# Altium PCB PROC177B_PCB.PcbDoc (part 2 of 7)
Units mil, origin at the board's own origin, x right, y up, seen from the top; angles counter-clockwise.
Board outline 4257.98 x 1561.15 mil, 4 copper layers (Top Layer, Int1 (GND), Int2 (PWR), Bottom Layer), stack 63.572 mil thick; 461 components, 307 nets, 1564 pads, 607 vias.
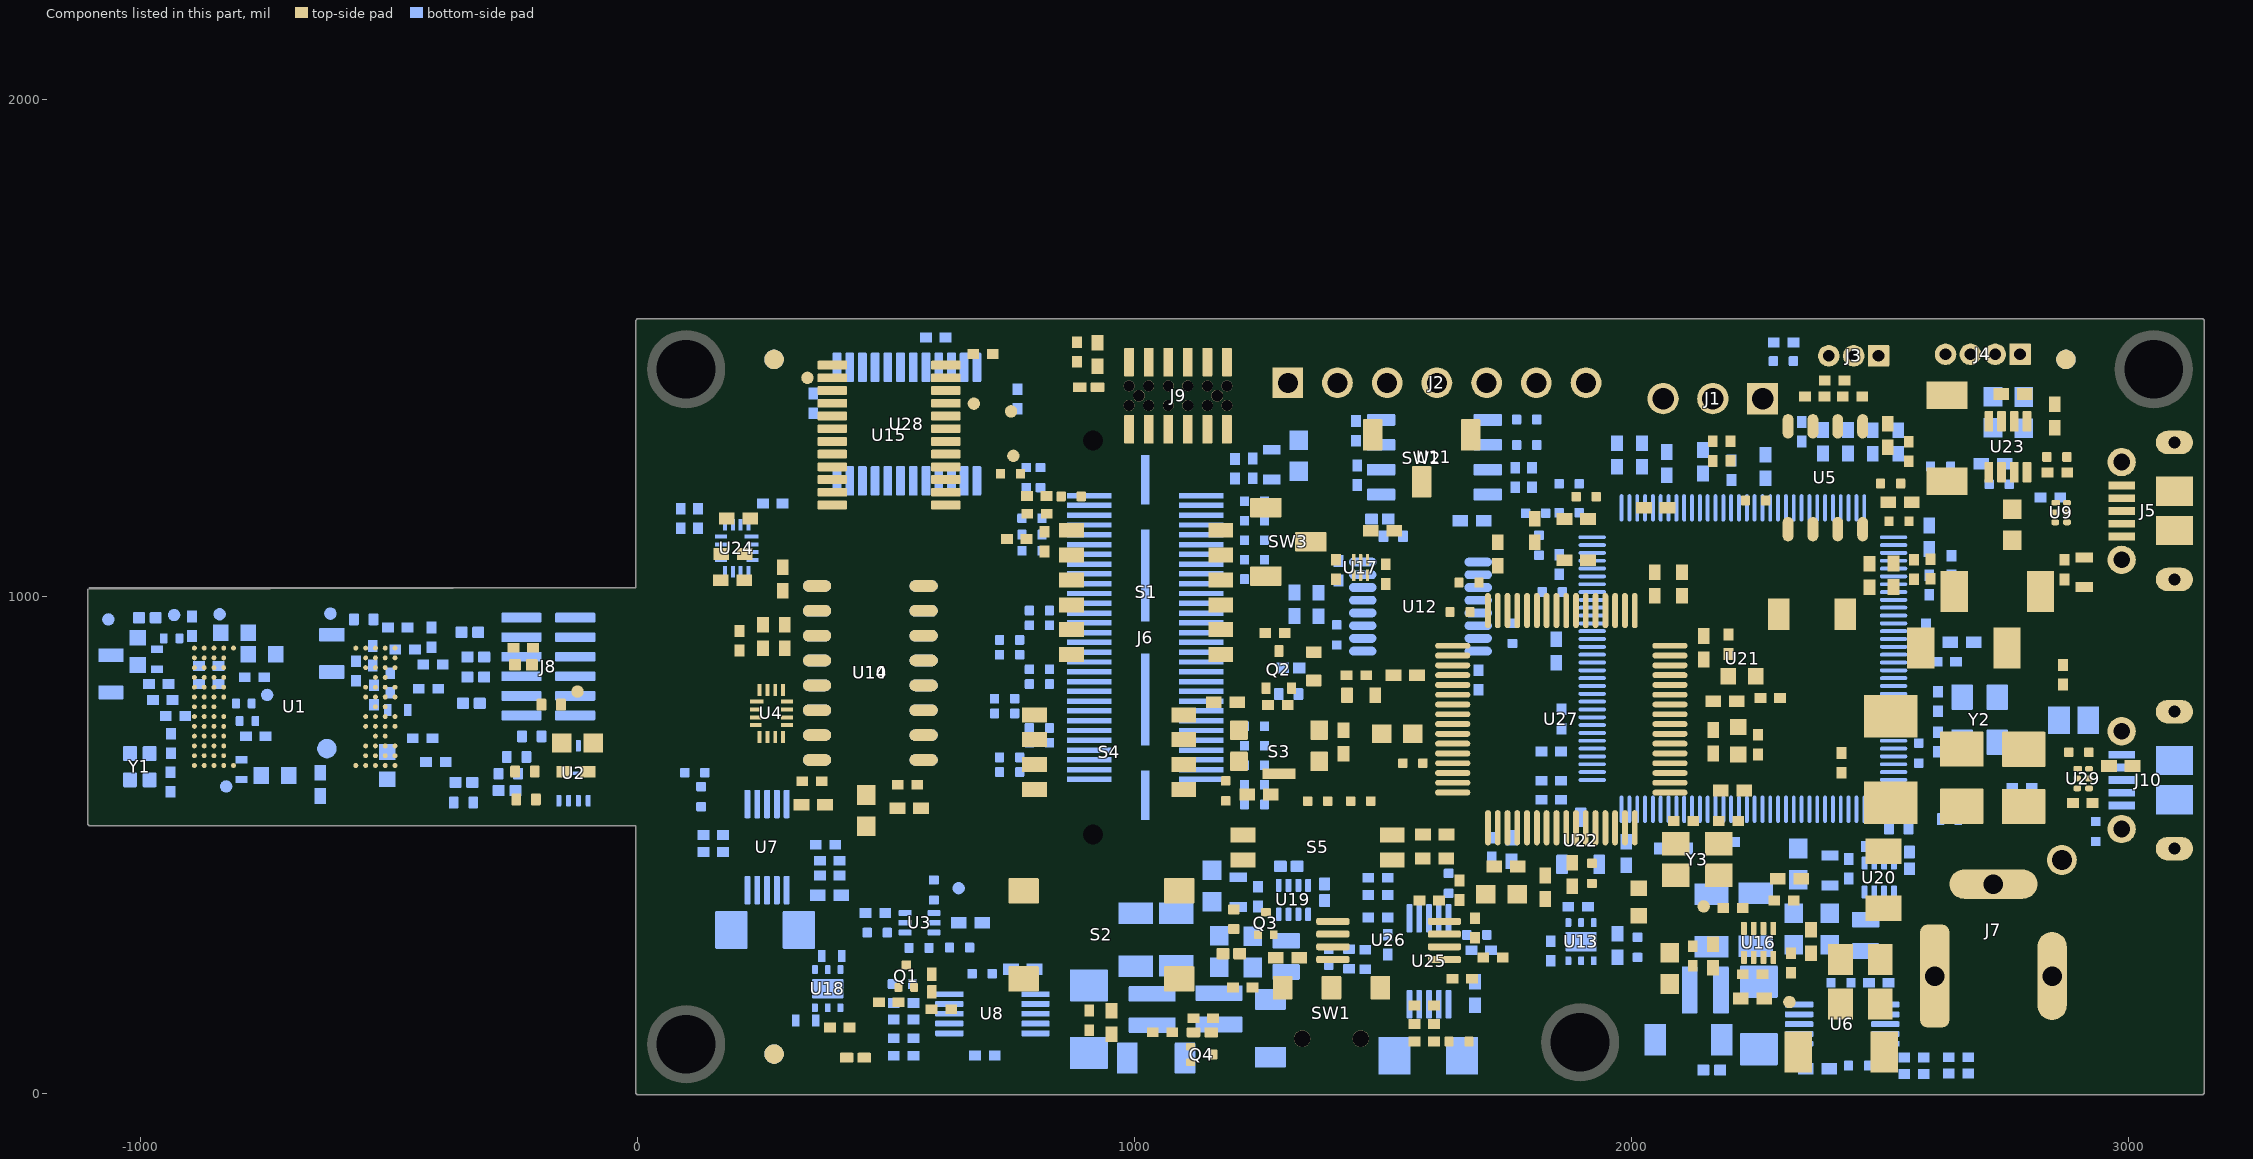
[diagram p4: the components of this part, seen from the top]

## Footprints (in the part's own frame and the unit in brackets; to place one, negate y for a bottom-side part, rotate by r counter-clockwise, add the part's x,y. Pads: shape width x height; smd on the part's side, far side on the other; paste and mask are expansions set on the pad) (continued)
0402_065L [mm] "0402"
  rect 0.6x0.5 smd: 1(-0.5,0) 2(0.5,0)
  body extent -0.55,-0.3 0.55,0.3, height 0.65
0402L [mm] "0402 from SM-752 data"
  rect 0.6x0.5 smd: 1(-0.5,0) 2(0.5,0)
  body extent -0.55,-0.3 0.55,0.3, height 0.6
0402S [mil] "Based on C0402S footprint from PADS legacy"
  rect 15x24 smd: 1(-20,0) 2(20,0)
  body extent -22,-12 22,12, height 24
0603 [mm] "0603 from SM-752 data"
  rect 1x0.95 smd: 1(-0.8,0) 2(0.8,0)
  silkscreen extent -1.52,-0.69 1.52,0.69, body extent -0.87,-0.47 0.87,0.47, height 1
0603L [mm] "0603 from SM-752 data"
  rect 0.8x0.85 smd: 1(-0.7,0) 2(0.7,0)
  silkscreen extent -0.07,-0.33 0.07,0.33, body extent -0.87,-0.47 0.87,0.47, height 1
0603S [mil]
  rect 20x35 smd: 1(-30,0) 2(30,0)
  body extent -34,-19 34,19, height 39
0805_HV [mil] "0805 with 30mil clearance between pads"
  rect 50x63 smd: 1(-40,0) 2(40,0)
  silkscreen extent -74,-40 74,40, body extent -43,-29 43,29, height 57
0805L [mm] "0805 from SM-752 data"
  rect 1.1x1.4 smd: 1(-0.75,0) 2(0.75,0)
  body extent -1.1,-0.72 1.1,0.72, height 1.45
1206 [mm] "1206 from SM-752 data"
  rect 1.3x1.85 smd: 1(-1.45,0) 2(1.45,0)
  silkscreen extent -2.4,-1.21 2.4,1.21, body extent -1.7,-0.9 1.7,0.9, height 1.35
1206_180 [mm] "1206_180"
  rect 1.1x1.6 smd: 1(-1.7,0) 2(1.7,0)
  silkscreen extent -0.9,-1 0.9,1, body extent -1.75,-0.95 1.75,0.95, height 1.8
1206_180L [mm] "1206_180"
  rect 1.1x1.75 smd: 1(-1.35,0) 2(1.35,0)
  silkscreen extent -0.4,-0.77 0.4,0.77, body extent -1.75,-0.95 1.75,0.95, height 1.8
3528-21 [mm] "Medium Density IPC, based on Kemet datasheet 2016-10-20"
  rrect6% 1.8x2.23 smd: 1(-1.46,0) 2(1.46,0)
  silkscreen extent -2.29,-1.5 0.76,1.5, body extent -1.85,-1.5 1.85,1.5, height 2.12
AMY0101A-MFG [mm]
  round 0.25 smd paste+0 mask+0.05: A1(-5.125,3) A2(-4.625,3) A3(-4.125,3) A4(-3.625,3) A5(-3.125,3) A6(3.125,3) A7(3.625,3) A8(4.125,3) A9(4.625,3) A10(5.125,3) B1(-5.125,2.5) B2(-4.625,2.5) B3(-4.125,2.5) B4(-3.625,2.5) B7(3.625,2.5) B8(4.125,2.5) B9(4.625,2.5) B10(5.125,2.5) C1(-5.125,2) C2(-4.625,2) C3(-4.125,2) C4(-3.625,2) C7(3.625,2) C8(4.125,2) C9(4.625,2) C10(5.125,2) D2(-4.625,1.5) D3(-4.125,1.5) D7(3.625,1.5) D8(4.125,1.5) D9(4.625,1.5) D10(5.125,1.5) E1(-5.125,1) E2(-4.625,1) E3(-4.125,1) E4(-3.625,1) E7(3.625,1) E8(4.125,1) E9(4.625,1) E10(5.125,1) F1(-5.125,0.5) F2(-4.625,0.5) F3(-4.125,0.5) F4(-3.625,0.5) F7(3.625,0.5) F8(4.125,0.5) F9(4.625,0.5) F10(5.125,0.5) G2(-4.625,0) G3(-4.125,0) G8(4.125,0) G9(4.625,0) G10(5.125,0) H1(-5.125,-0.5) H2(-4.625,-0.5) H3(-4.125,-0.5) H4(-3.625,-0.5) H7(3.625,-0.5) H8(4.125,-0.5) H9(4.625,-0.5) H10(5.125,-0.5) J1(-5.125,-1) J2(-4.625,-1) J3(-4.125,-1) J4(-3.625,-1) J7(3.625,-1) J8(4.125,-1) J9(4.625,-1) J10(5.125,-1) K2(-4.625,-1.5) K3(-4.125,-1.5) K7(3.625,-1.5) K8(4.125,-1.5) K9(4.625,-1.5) K10(5.125,-1.5) L1(-5.125,-2) L2(-4.625,-2) L3(-4.125,-2) L4(-3.625,-2) L7(3.625,-2) L8(4.125,-2) L9(4.625,-2) L10(5.125,-2) M1(-5.125,-2.5) M2(-4.625,-2.5) M3(-4.125,-2.5) M4(-3.625,-2.5) M7(3.625,-2.5) M8(4.125,-2.5) M9(4.625,-2.5) M10(5.125,-2.5) N1(-5.125,-3) N2(-4.625,-3) N3(-4.125,-3) N4(-3.625,-3) N5(-3.125,-3) N6(3.125,-3) N7(3.625,-3) N8(4.125,-3) N9(4.625,-3) N10(5.125,-3)
  silkscreen extent -2.63,-3.4 2.63,3.4, body extent -6,-3.9 6,3.9, height 0.25
APHHS1005_Green [mm] "SMD, 2-Leads, Body 1x0.5mm"
  rrect20% 0.7x0.5 smd: 1(-0.45,0) 2(0.45,0)
  silkscreen extent -0.8,-0.65 1.2,0.65, body extent -0.5,-0.25 0.5,0.25, height 0.5
APHHS1005_Red [mm] "SMD, 2-Leads, Body 1x0.5mm"
  rrect20% 0.7x0.5 smd: 1(-0.45,0) 2(0.45,0)
  silkscreen extent 0.9,-0.31 1,0.33, body extent -0.5,-0.25 0.5,0.25, height 0.5
AssemblyNote [mil] "Assembly Note"
AssemblyNoteLabel [mil] "Assembly Note for PCB Labels"
CE_Mark_5mm [mil] "Minimum text height for CE Mark"
  silkscreen extent -138,-98 138,98
CONN_105017-0001 [mm] "Molex Micro USB-B"
  rect 0.4x1.35 smd: 1(-1.3,1.35) 2(-0.65,1.35) 3(0,1.35) 4(0.65,1.35) 5(1.3,1.35)
  oval 1.2x1.9 hole 0.6 slot 1.3 at 90 deg: 6(-3.5,-1.35) 9(3.5,-1.35)
  rect 1.5x1.9 smd: 7(-1,-1.35) 8(1,-1.35)
  round 1.45 hole 0.85: 10(2.5,1.35) 11(-2.5,1.35)
  Top Layer region: 3.499,-0.399 2.299,-0.399 2.299,-2.299 3.499,-2.299
  Top Layer region: -3.5,-2.299 -2.3,-2.299 -2.3,-0.399 -3.5,-0.399
  silkscreen extent -4.1,-0.2 4.1,1.4, body extent -4.1,-3.93 4.1,1.5, height 2.72
CUI_PJ-002AH [mm] "DC POWER JACK, R/A, TH"
  rrect50% 1.5x5.25 hole 1 square: 1(-3,0)
  oval 1.5x4.5 hole 1 square: 2(3,0)
  oval 4.5x1.5 hole 1 square: 3(0,4.7)
  silkscreen extent -4.1,-4.5 10.7,4.5, body extent -3.7,-4.5 10.7,4.9, height 11
D0008A_L [mm] "SOIC, 8-Leads, Body 4.9x3.9mm, Pitch 1.27mm, IPC High Density"
  oval 1.25x0.55 smd: 1(-2.625,1.905) 2(-2.625,0.635) 3(-2.625,-0.635) 4(-2.625,-1.905) 5(2.625,-1.905) 6(2.625,-0.635) 7(2.625,0.635) 8(2.625,1.905)
  silkscreen extent -3.1,2.5 0.9,2.5, body extent -3,-2.45 3,2.45, height 1.63
D0016A_N [mm] "SOIC, 16-Leads, Body 9.9x3.9mm, Pitch 1.27mm, IPC Medium Density"
  oval 1.45x0.6 smd: 1(-2.725,4.445) 2(-2.725,3.175) 3(-2.725,1.905) 4(-2.725,0.635) 5(-2.725,-0.635) 6(-2.725,-1.905) 7(-2.725,-3.175) 8(-2.725,-4.445) 9(2.725,-4.445) 10(2.725,-3.175) 11(2.725,-1.905) 12(2.725,-0.635) 13(2.725,0.635) 14(2.725,1.905) 15(2.725,3.175) 16(2.725,4.445)
  silkscreen extent -3.3,-5 0.9,5, body extent -3,-4.95 3,4.95, height 1.6
DBZ0003A_N [mm] "SOT23, 3-Leads, Body 2.9x1.3mm, Pitch 0.95mm, Lead Span 2.4mm, IPC Medium Density"
  rrect17% 1x0.6 smd: 1(-1.2,0.95) 2(-1.2,-0.95) 3(1.2,0)
  silkscreen extent 0.2,-1.5 0.7,1.5, body extent -1.26,-1.46 1.26,1.46, height 0.98
DDF0008A-MFG [mm]
  rrect22% 1.05x0.45 smd paste+0 mask+0: 1(-1.3,0.975) 2(-1.3,0.325) 3(-1.3,-0.325) 4(-1.3,-0.975) 5(1.3,-0.975) 6(1.3,-0.325) 7(1.3,0.325) 8(1.3,0.975)
  silkscreen extent -2.5,-1.48 0.4,1.48, body extent -1.41,-1.45 1.41,1.45, height 1.1
DGS0010A-MFG [mm]
  rrect33% 1.45x0.3 smd paste+0 mask+0: 1(-2.2,1) 2(-2.2,0.5) 3(-2.2,0) 4(-2.2,-0.5) 5(-2.2,-1) 6(2.2,-1) 7(2.2,-0.5) 8(2.2,0) 9(2.2,0.5) 10(2.2,1)
  silkscreen extent -3.6,-1.55 1.05,1.55, body extent -2.45,-1.5 2.45,1.5, height 1.1
DRL0006A [mm] "SOTFL, 6-Flat Leads, Body 1.2x1.6x0.6mm, Pitch 0.5mm, TI recommended"
  rrect33% 0.67x0.3 smd: 1(-0.74,0.5) 2(-0.74,0) 3(-0.74,-0.5) 4(0.74,-0.5) 5(0.74,0) 6(0.74,0.5)
  silkscreen extent -0.5,-0.95 0.5,-0.95, body extent -0.8,-0.8 0.8,0.8, height 0.61
DRL0008A-MFG [mm]
  rrect33% 0.67x0.3 smd paste+0 mask+0: 1(-0.74,0.75) 2(-0.74,0.25) 3(-0.74,-0.25) 4(-0.74,-0.75) 5(0.74,-0.75) 6(0.74,-0.25) 7(0.74,0.25) 8(0.74,0.75)
  silkscreen extent -1.14,-1.28 0.65,1.57, body extent -1.17,-1.35 1.18,1.35, height 0.25
DRV0006A [mm] "SON, 6-Leads, Body 2x2mm, Pitch 0.65mm, Thermal Pad 1.6x1mm, TI Recommended"
  rrect33% 0.45x0.3 smd: 1(-0.975,0.65) 2(-0.975,0) 3(-0.975,-0.65) 4(0.975,-0.65) 5(0.975,0) 6(0.975,0.65)
  rrect14% 1x0.7 on Bottom Paste: 7(0,-0.45) 7(0,0.45)
  rrect10% 1x1.6 smd paste-0.5: 7(0,0)
  silkscreen extent -1.05,-1.2 1.05,1.2, body extent -1.05,-1.05 1.05,1.05, height 0.81
DRY0006A [mm] "USON-6"
  rrect67% 0.45x0.3 smd paste-0.05 mask-0.05: 1(-0.275,0.5)
  rrect67% 0.4x0.3 smd paste-0.05 mask-0.05: 2(-0.3,0) 3(-0.3,-0.5) 4(0.3,-0.5) 5(0.3,0) 6(0.3,0.5)
  body extent -0.5,-0.72 0.5,0.73, height 0.58
DSF0006A [mm] "TI recommended land pattern"
  rrect59% 0.6x0.17 smd mask+0.045: 1(-0.4,0.35) 2(-0.4,0) 3(-0.4,-0.35) 4(0.4,-0.35) 5(0.4,0) 6(0.4,0.35)
  silkscreen extent -0.6,-0.63 0.6,0.63, body extent -0.5,-0.5 0.5,0.5, height 0.48
FCC_disclaimer [mil]
Fiducial10-20 [mm]
  round 1 smd mask+0.5: 1(0,0)
  Top Layer keep-out circle w1.178: c0,0 r0.5
FP-0022288072_HDR7-MFG [mm]
  rrect6% 1.57x1.57 hole 1.02 paste-2539.97 mask+0: 1(-7.62,-2.925)
  round 1.57 hole 1.02 paste-2539.97 mask+0: 2(-5.08,-2.925) 3(-2.54,-2.925) 4(0,-2.925) 5(2.54,-2.925) 6(5.08,-2.925) 7(7.62,-2.925)
  silkscreen extent -9.11,-3.05 9.02,1.27, body extent -9.12,-3.81 9.12,7.95, height 0.25
FP-AYZ0102AGRLC_SMT_SW_7MM2_5MM3-MFG [mm]
  rrect10% 1x1.2 smd paste+0 mask+0: 1(-2.5,3.1) 2(0,3.1) 3(2.5,3.1)
  round 0.85 hole 0.85 unplated paste-2539.97 mask+0: ""(-1.5,0.5) ""(1.5,0.5)
  silkscreen extent -3.6,-2 3.6,3.38, body extent -3.7,-2.1 3.7,3.8, height 0.25
FP-BC050-12A-K0-0200-0160-0480-LB_HDR12-MFG [mm]
  rrect20% 0.5x2.05 smd paste+0 mask+0: 1(-2.5,-1.375) 2(-2.5,1.375) 3(-1.5,-1.375) 4(-1.5,1.375) 5(-0.5,-1.375) 6(-0.5,1.375) 7(0.5,-1.375) 8(0.5,1.375) 9(1.5,-1.375) 10(1.5,1.375) 11(2.5,-1.375) 12(2.5,1.375)
  silkscreen extent -3.17,-2.87 2.95,1.63, body extent -3,-2.4 3,2.4, height 4.1
FP-BC084-12-A-0390-L-C_CONN_RCPT12-MFG [mm]
  rrect20% 0.5x1.47 smd paste+0 mask+0: 1(-2.5,-1.715) 2(-2.5,1.715) 3(-1.5,-1.715) 4(-1.5,1.715) 5(-0.5,-1.715) 6(-0.5,1.715) 7(0.5,-1.715) 8(0.5,1.715) 9(1.5,-1.715) 10(1.5,1.715) 11(2.5,-1.715) 12(2.5,1.715)
  round 0.56 hole 0.56 unplated paste-2539.97 mask+0: ""(-2.5,-0.5) ""(-2.5,0.5) ""(-1.5,-0.5) ""(-1.5,0.5) ""(-0.5,-0.5) ""(-0.5,0.5) ""(0.5,-0.5) ""(0.5,0.5) ""(1.5,-0.5) ""(1.5,0.5) ""(2.5,-0.5) ""(2.5,0.5)
  round 0.6 hole 0.6 unplated paste-2539.97 mask+0: ""(-2,0) ""(2,0)
  silkscreen extent -3.4,-3.13 3.4,1.33, body extent -3.5,-2.55 3.5,2.55, height 0.25
FP-CJS-1200A1_SMT3-MFG [mm]
  rrect10% 1x1.6 smd paste+0 mask+0: 1(-1.75,-1.15) 2(0,1.15) 3(1.75,-1.15)
  silkscreen extent -3.46,-1.4 2.85,1.4, body extent -2.95,-2.05 2.95,2.05, height 0.25
FP-CRCW040218K0FKEDC_0402-IPC_B [mil]
  rrect17% 25.97x22.54 smd paste+0 mask+0: 1(-16.78,0) 2(16.78,0)
  silkscreen extent -30,27 30,27, body extent -20,-10 20,10, height 14
FP-CRCW040240K2FKEDC_0402-MFG [mm]
  rrect25% 0.4x0.6 smd paste+0 mask+0: 1(-0.45,0) 2(0.45,0)
  silkscreen extent -0.55,-0.67 0.55,0.67, body extent -0.5,-0.25 0.5,0.25, height 0.35
FP-CRCW0402100KFKEDC_0402-IPC_B [mil]
  rrect17% 25.97x22.54 smd paste+0 mask+0: 1(-16.78,0) 2(16.78,0)
  body extent -20,-10 20,10, height 14
"FP-DFE201210U-R47M=P2_0805 (2012)-MFG" [mm]
  rrect13% 0.8x1.4 smd paste+0 mask+0: 1(-0.8,0) 2(0.8,0)
  silkscreen extent -1.2,-1.07 1.2,1.08, body extent -1,-0.6 1,0.6, height 1
FP-ECS-160-8-33Q-RES-TR_SMT4_3MM2_2MM5-MFG [mm]
  rrect9% 1.3x1.1 smd paste+0 mask+0: 1(-1.15,-0.9) 2(1.15,-0.9) 3(1.15,0.9) 4(-1.15,0.9)
  silkscreen extent -1.52,-1.96 0.13,1.3, body extent -1.6,-1.25 1.6,1.25, height 0.8
FP-ERJ-2GE0R00X_0402-MFG [mm]
  rrect21% 0.475x0.5 smd paste+0 mask+0: 1(-0.512,0) 2(0.513,0)
  silkscreen extent -0.53,0.63 0.53,0.63, body extent -0.5,-0.25 0.5,0.25, height 0.4
FP-GJM1555C1H100FB01D_0402-MFG [mm]
  rrect25% 0.4x0.5 smd paste+0 mask+0: 1(-0.4,0) 2(0.4,0)
  silkscreen extent -0.53,-0.63 0.53,0.63, body extent -0.5,-0.25 0.5,0.25, height 0.55
FP-GRM21BR71C475KE51L_0805-MFG [mm]
  rrect14% 0.7x1.3 smd paste+0 mask+0: 1(-0.95,0) 2(0.95,0)
  silkscreen extent -0.23,-0.7 0.23,0.7, body extent -1,-0.63 1,0.63, height 1.4
FP-GRM31CR70J226ME19K_1206-MFG [mm]
  rrect10% 1.05x1.6 smd paste+0 mask+0: 1(-1.475,0) 2(1.475,0)
  silkscreen extent -0.58,-0.9 0.58,0.9, body extent -1.6,-0.8 1.6,0.8, height 1.8
FP-GRM155C80J105KA12D_0402-MFG [mm]
  rrect25% 0.4x0.5 smd paste+0 mask+0: 1(-0.4,0) 2(0.4,0)
  silkscreen extent -0.5,-0.47 0.54,0.55, body extent -0.5,-0.25 0.5,0.25, height 0.55
FP-JS102011JCQN_SMD3-MFG [mm]
  rrect10% 1x1.6 smd paste+0 mask+0: 1(-2.5,-1.2) 2(0,1.2) 3(2.5,-1.2)
  silkscreen extent -4.25,-2.67 4.25,1.8, body extent -4.35,-2.1 4.35,2.1, height 0.25
"FP-LQM2MPZR10MJHL_0806 (2016)-MFG" [mm]
  rrect13% 0.8x2.4 smd paste-1000 mask-1000: 1(-0.8,0) 2(0.8,0)
  silkscreen extent -1.1,-1.5 1.1,1.5, body extent -1,-0.8 1,0.8, height 1.2
FP-M50-3930342_HDR3-MFG [mm]
  rrect9% 1.1x1.1 hole 0.6 paste-2539.97 mask+0: 1(-1.27,1)
  round 1.1 hole 0.6 paste-2539.97 mask+0: 2(0,1) 3(1.27,1)
  silkscreen extent -2.41,-0.6 2.15,1.1, body extent -1.91,-4.5 1.91,1.2, height 2.3
FP-M50-3930442_HDR4-Recommended_Land_Pattern [mm]
  rrect9% 1.1x1.1 hole 0.6 paste-2539.97 mask+0: 1(-1.905,1)
  round 1.1 hole 0.6 paste-2539.97 mask+0: 2(-0.635,1) 3(0.635,1) 4(1.905,1)
  body extent -2.54,-4.5 2.54,1.2, height 2.3
FP-RC0402FR-071KL_0402-IPC_B [mil]
  rrect17% 24.23x22.54 smd paste+0 mask+0: 1(-16.87,0) 2(16.87,0)
  silkscreen extent -29,-18 29,27, body extent -20,-10 20,10, height 16
FP-RC0402FR-0710KL_0402-IPC_B [mil]
  rrect17% 24.23x22.54 smd paste+0 mask+0: 1(-16.87,0) 2(16.87,0)
  silkscreen extent -29,21 29,21, body extent -20,-10 20,10, height 16
FP-RC0402FR-1047K5L_0402-MFG [mm]
  rrect20% 0.5x0.6 smd paste+0 mask+0: 1(-0.5,0) 2(0.5,0)
  body extent -0.5,-0.25 0.5,0.25, height 0.4
FP-RC0402JR-070RP_0402-MFG [mm]
  rrect20% 0.5x0.6 smd paste+0 mask+0: 1(-0.5,0) 2(0.5,0)
  silkscreen extent -0.5,-0.67 0.5,0.67, body extent -0.5,-0.25 0.5,0.25, height 0.4
FP-RT0402FRE0733R2L_0402-MFG [mm]
  rrect20% 0.5x0.6 smd paste+0 mask+0: 1(-0.5,0) 2(0.5,0)
  silkscreen extent -0.5,-0.71 0.5,0.7, body extent -0.85,-0.4 0.85,0.4, height 0.25
FP-SSM3K35AMFV,L3F_SOT-723-MFG [mm]
  rrect25% 0.45x0.4 smd paste+0 mask+0: 1(-0.575,0.4) 2(-0.575,-0.4)
  rrect22% 0.45x0.5 smd paste+0 mask+0: 3(0.575,0)
  silkscreen extent -0.43,-0.73 0.43,0.8, body extent -0.9,-0.72 0.9,0.72, height 0.25
FP-WR04X1003FTL_0402-IPC_B [mil]
  rrect17% 24.23x22.54 smd paste+0 mask+0: 1(-16.87,0) 2(16.87,0)
  silkscreen extent -29,-27 29,27, body extent -20,-10 20,10, height 16
FP-WR04X6802FTL_0402-MFG [mm]
  rrect20% 0.5x0.6 smd paste+0 mask+0: 1(-0.5,0) 2(0.5,0)
  silkscreen extent -0.5,0.64 0.5,0.64, body extent -0.5,-0.25 0.5,0.25, height 0.4
FP-WSL1206R0200FEB_1206-MFG [mm]
  rrect6% 1.65x1.93 smd paste+0 mask+0: 1(-1.725,0) 2(1.725,0)
  silkscreen extent -0.53,-0.93 0.53,0.93, body extent -1.6,-0.8 1.6,0.8, height 0.89
FP-WSL1206R0400FEB_1206-MFG [mm]
  rrect6% 1.65x1.93 smd paste+0 mask+0: 1(-1.725,0) 2(1.725,0)
  silkscreen extent -0.53,-0.93 0.53,0.93, body extent -1.6,-0.8 1.6,0.8, height 0.89
FP-XRCGB40M000F1S2GR0_SMT_CRYSTAL_2MM0_1MM6-MFG [mm]
  rrect14% 0.75x0.7 smd paste+0 mask+0: 1(-0.675,-0.5) 2(0.675,-0.5) 3(0.675,0.5) 4(-0.675,0.5)
  silkscreen extent -1.43,-1.52 1.43,0.85, body extent -1,-0.8 1,0.8, height 0.7
LQFP64_N [mm] "Thin QFP, 64-Leads, Body 10x10mm, Pitch 0.5mm, IPC Medium Density"
  oval 1.8x0.3 smd: 1(-5.55,3.75) 2(-5.55,3.25) 3(-5.55,2.75) 4(-5.55,2.25) 5(-5.55,1.75) 6(-5.55,1.25) 7(-5.55,0.75) 8(-5.55,0.25) 9(-5.55,-0.25) 10(-5.55,-0.75) 11(-5.55,-1.25) 12(-5.55,-1.75) 13(-5.55,-2.25) 14(-5.55,-2.75) 15(-5.55,-3.25) 16(-5.55,-3.75) 33(5.55,-3.75) 34(5.55,-3.25) 35(5.55,-2.75) 36(5.55,-2.25) 37(5.55,-1.75) 38(5.55,-1.25) 39(5.55,-0.75) 40(5.55,-0.25) 41(5.55,0.25) 42(5.55,0.75) 43(5.55,1.25) 44(5.55,1.75) 45(5.55,2.25) 46(5.55,2.75) 47(5.55,3.25) 48(5.55,3.75)
  oval 0.3x1.8 smd: 17(-3.75,-5.55) 18(-3.25,-5.55) 19(-2.75,-5.55) 20(-2.25,-5.55) 21(-1.75,-5.55) 22(-1.25,-5.55) 23(-0.75,-5.55) 24(-0.25,-5.55) 25(0.25,-5.55) 26(0.75,-5.55) 27(1.25,-5.55) 28(1.75,-5.55) 29(2.25,-5.55) 30(2.75,-5.55) 31(3.25,-5.55) 32(3.75,-5.55) 49(3.75,5.55) 50(3.25,5.55) 51(2.75,5.55) 52(2.25,5.55) 53(1.75,5.55) 54(1.25,5.55) 55(0.75,5.55) 56(0.25,5.55) 57(-0.25,5.55) 58(-0.75,5.55) 59(-1.25,5.55) 60(-1.75,5.55) 61(-2.25,5.55) 62(-2.75,5.55) 63(-3.25,5.55) 64(-3.75,5.55)
  silkscreen extent -6.96,-4.25 4.25,4.25, body extent -5,-5 5,5, height 1.6
NDK_NX3225SA [mm] "NDK"
  rect 1.2x1.4 smd: 1(-0.8,1.1) 2(-0.8,-1.1) 3(0.8,-1.1) 4(0.8,1.1)
  body extent -1.3,-1.65 1.3,1.65, height 0.7
PDT0128A [mm] "Thin QFP, 128-Leads, Body 14x14mm, Pitch 0.4mm"
  oval 1.4x0.2 smd: 1(-7.7,6.2) 2(-7.7,5.8) 3(-7.7,5.4) 4(-7.7,5) 5(-7.7,4.6) 6(-7.7,4.2) 7(-7.7,3.8) 8(-7.7,3.4) 9(-7.7,3) 10(-7.7,2.6) 11(-7.7,2.2) 12(-7.7,1.8) 13(-7.7,1.4) 14(-7.7,1) 15(-7.7,0.6) 16(-7.7,0.2) 17(-7.7,-0.2) 18(-7.7,-0.6) 19(-7.7,-1) 20(-7.7,-1.4) 21(-7.7,-1.8) 22(-7.7,-2.2) 23(-7.7,-2.6) 24(-7.7,-3) 25(-7.7,-3.4) 26(-7.7,-3.8) 27(-7.7,-4.2) 28(-7.7,-4.6) 29(-7.7,-5) 30(-7.7,-5.4) 31(-7.7,-5.8) 32(-7.7,-6.2) 65(7.7,-6.2) 66(7.7,-5.8) 67(7.7,-5.4) 68(7.7,-5) 69(7.7,-4.6) 70(7.7,-4.2) 71(7.7,-3.8) 72(7.7,-3.4) 73(7.7,-3) 74(7.7,-2.6) 75(7.7,-2.2) 76(7.7,-1.8) 77(7.7,-1.4) 78(7.7,-1) 79(7.7,-0.6) 80(7.7,-0.2) 81(7.7,0.2) 82(7.7,0.6) 83(7.7,1) 84(7.7,1.4) 85(7.7,1.8) 86(7.7,2.2) 87(7.7,2.6) 88(7.7,3) 89(7.7,3.4) 90(7.7,3.8) 91(7.7,4.2) 92(7.7,4.6) 93(7.7,5) 94(7.7,5.4) 95(7.7,5.8) 96(7.7,6.2)
  oval 0.2x1.4 smd: 33(-6.2,-7.7) 34(-5.8,-7.7) 35(-5.4,-7.7) 36(-5,-7.7) 37(-4.6,-7.7) 38(-4.2,-7.7) 39(-3.8,-7.7) 40(-3.4,-7.7) 41(-3,-7.7) 42(-2.6,-7.7) 43(-2.2,-7.7) 44(-1.8,-7.7) 45(-1.4,-7.7) 46(-1,-7.7) 47(-0.6,-7.7) 48(-0.2,-7.7) 49(0.2,-7.7) 50(0.6,-7.7) 51(1,-7.7) 52(1.4,-7.7) 53(1.8,-7.7) 54(2.2,-7.7) 55(2.6,-7.7) 56(3,-7.7) 57(3.4,-7.7) 58(3.8,-7.7) 59(4.2,-7.7) 60(4.6,-7.7) 61(5,-7.7) 62(5.4,-7.7) 63(5.8,-7.7) 64(6.2,-7.7) 97(6.2,7.7) 98(5.8,7.7) 99(5.4,7.7) 100(5,7.7) 101(4.6,7.7) 102(4.2,7.7) 103(3.8,7.7) 104(3.4,7.7) 105(3,7.7) 106(2.6,7.7) 107(2.2,7.7) 108(1.8,7.7) 109(1.4,7.7) 110(1,7.7) 111(0.6,7.7) 112(0.2,7.7) 113(-0.2,7.7) 114(-0.6,7.7) 115(-1,7.7) 116(-1.4,7.7) 117(-1.8,7.7) 118(-2.2,7.7) 119(-2.6,7.7) 120(-3,7.7) 121(-3.4,7.7) 122(-3.8,7.7) 123(-4.2,7.7) 124(-4.6,7.7) 125(-5,7.7) 126(-5.4,7.7) 127(-5.8,7.7) 128(-6.2,7.7)
  silkscreen extent -7.7,-6.3 6.3,6.99, body extent -8,-8 8,8, height 1.07
PW0016A_N [mm] "TSOP, 16-Leads, Body 5x4.4mm, Pitch 0.65mm, IPC Medium Density"
  oval 1.4x0.45 smd: 1(-2.95,2.275) 2(-2.95,1.625) 3(-2.95,0.975) 4(-2.95,0.325) 5(-2.95,-0.325) 6(-2.95,-0.975) 7(-2.95,-1.625) 8(-2.95,-2.275) 9(2.95,-2.275) 10(2.95,-1.625) 11(2.95,-0.975) 12(2.95,-0.325) 13(2.95,0.325) 14(2.95,0.975) 15(2.95,1.625) 16(2.95,2.275)
  silkscreen extent -3.5,-2.55 1.85,2.75, body extent -3.21,-2.5 3.21,2.5, height 1
PW0024A-MFG [mm]
  rrect22% 1.5x0.45 smd paste+0 mask+0: 1(-2.9,3.575) 2(-2.9,2.925) 3(-2.9,2.275) 4(-2.9,1.625) 5(-2.9,0.975) 6(-2.9,0.325) 7(-2.9,-0.325) 8(-2.9,-0.975) 9(-2.9,-1.625) 10(-2.9,-2.275) 11(-2.9,-2.925) 12(-2.9,-3.575) 13(2.9,-3.575) 14(2.9,-2.925) 15(2.9,-2.275) 16(2.9,-1.625) 17(2.9,-0.975) 18(2.9,-0.325) 19(2.9,0.325) 20(2.9,0.975) 21(2.9,1.625) 22(2.9,2.275) 23(2.9,2.925) 24(2.9,3.575)
  silkscreen extent -4.16,-3.95 1.78,3.95, body extent -3.75,-4.2 3.75,4.2, height 0.25
RSV0016A [mm] "QFN, 16-Leads, Body 1.8x2.6mm, Pitch 0.4mm, TI Recommended"
  rect 0.7x0.2 smd: 1(-0.75,0.6)
  rect 0.6x0.2 smd: 2(-0.8,0.2) 3(-0.8,-0.2) 4(-0.8,-0.6) 9(0.8,-0.6) 10(0.8,-0.2) 11(0.8,0.2) 12(0.8,0.6)
  rect 0.2x0.6 smd: 5(-0.6,-1.2) 6(-0.2,-1.2) 7(0.2,-1.2) 8(0.6,-1.2) 13(0.6,1.2) 14(0.2,1.2) 15(-0.2,1.2) 16(-0.6,1.2)
  silkscreen extent -1.08,-1.33 1.08,1.45, body extent -0.93,-1.32 0.92,1.33, height 0.56
Samtec_QSH-030-01-X-D-A [mm] "Receptacle, 0.5 mm, 30x2, TH"
  rect 2.27x0.279 smd: 1(-2.865,7.25) 2(2.865,7.25) 3(-2.865,6.75) 4(2.865,6.75) 5(-2.865,6.25) 6(2.865,6.25) 7(-2.865,5.75) 8(2.865,5.75) 9(-2.865,5.25) 10(2.865,5.25) 11(-2.865,4.75) 12(2.865,4.75) 13(-2.865,4.25) 14(2.865,4.25) 15(-2.865,3.75) 16(2.865,3.75) 17(-2.865,3.25) 18(2.865,3.25) 19(-2.865,2.75) 20(2.865,2.75) 21(-2.865,2.25) 22(2.865,2.25) 23(-2.865,1.75) 24(2.865,1.75) 25(-2.865,1.25) 26(2.865,1.25) 27(-2.865,0.75) 28(2.865,0.75) 29(-2.865,0.25) 30(2.865,0.25) 31(-2.865,-0.25) 32(2.865,-0.25) 33(-2.865,-0.75) 34(2.865,-0.75) 35(-2.865,-1.25) 36(2.865,-1.25) 37(-2.865,-1.75) 38(2.865,-1.75) 39(-2.865,-2.25) 40(2.865,-2.25) 41(-2.865,-2.75) 42(2.865,-2.75) 43(-2.865,-3.25) 44(2.865,-3.25) 45(-2.865,-3.75) 46(2.865,-3.75) 47(-2.865,-4.25) 48(2.865,-4.25) 49(-2.865,-4.75) 50(2.865,-4.75) 51(-2.865,-5.25) 52(2.865,-5.25) 53(-2.865,-5.75) 54(2.865,-5.75) 55(-2.865,-6.25) 56(2.865,-6.25) 57(-2.865,-6.75) 58(2.865,-6.75) 59(-2.865,-7.25) 60(2.865,-7.25)
  round 0 hole 1.02 unplated mask+0.127: MH1(2.67,10.065) MH2(2.67,-10.065)
  rect 0.43x2.54 smd: MP1(0,8.065) MP4(0,-8.065)
  rect 0.43x4.7 smd: MP2(0,3.175) MP3(0,-3.175)
  silkscreen extent -3.9,-10.66 3.62,10.66, body extent -3.75,-10.64 3.75,10.67, height 3.25
SMB [mil] "Molded Diode, 2-Leads, Body 5.4x3.6mm, IPC Medium Density, based on OnSemi component dimensions"
  rect 85x107.99 smd: 1(-87.01,0) 2(87.01,0)
  silkscreen extent -155,-82 125,82, body extent -106,-71 106,71, height 91
SOD-128 [mm] "SMD, 2-Leads, Body 4x2.7mm, Height 1.1mm"
  rect 1.4x2.1 smd paste-0.1: 1(-2.2,0) 2(2.2,0)
  silkscreen extent -3.45,-1.35 2.95,1.35, body extent -2.5,-1.35 2.5,1.35, height 1.11
SOIC-8 [mm] "duplicate of SO-8.  SOIC, 8-Leads, Body 5.0x4.0mm (max), Pitch 1.27mm, IPC Medium Density"
  rrect17% 1.45x0.6 smd: 1(-2.725,1.905) 2(-2.725,0.635) 3(-2.725,-0.635) 4(-2.725,-1.905) 5(2.725,-1.905) 6(2.725,-0.635) 7(2.725,0.635) 8(2.725,1.905)
  silkscreen extent -1.37,-2.5 1.17,2.5, body extent -3,-2.45 3,2.45, height 1.63
SOT-323 [mm] "Diodes Inc recommended land pattern.  2016-02-24"
  rrect21% 0.6x0.47 smd: 1(-0.95,0.65) 2(-0.95,-0.65) 3(0.95,0)
  silkscreen extent -1.14,-1.22 0.78,1.22, body extent -1.13,-1.13 1.12,1.12, height 1.13
SW_218-2LP [mm] "SMD, 4-Leads, Body 3.71x5.8mm, Pitch 1.27mm"
  rect 1.27x0.76 smd: 1(-3.81,0.635) 2(-3.81,-0.635) 3(3.81,-0.635) 4(3.81,0.635)
  silkscreen extent -2.9,-1.86 2.9,2.09, body extent -4.22,-1.86 4.22,1.85, height 2.62
SW_218-4LPST [mil] "CTS Components"
  rect 50x30 smd: 1(-150,75) 2(-150,25) 3(-150,-25) 4(-150,-75) 5(150,-75) 6(150,-25) 7(150,25) 8(150,75)
  silkscreen extent -114,-123 114,123, body extent -166,-123 166,123, height 104
SW_218-6LPST [mm] "SMD, 12-Leads, Body 5.8x8.79mm"
  rect 1.27x0.76 smd: 1(-3.81,3.175) 2(-3.81,1.905) 3(-3.81,0.635) 4(-3.81,-0.635) 5(-3.81,-1.905) 6(-3.81,-3.175) 7(3.81,-3.175) 7(3.81,-3.175) 8(3.81,-1.905) 9(3.81,-0.635) 10(3.81,0.635) 11(3.81,1.905) 12(3.81,3.175)
  silkscreen extent -2.9,-4.4 2.9,4.7, body extent -4.22,-4.4 4.22,4.39, height 2.62
SW_KMR243GLFG [mm] "SMD, 5-Leads, Body 4.2x2.8mm"
  rrect11% 0.9x1 smd: 1(-2.05,0.8) 2(2.05,0.8) 3(-2.05,-0.8) 4(2.05,-0.8)
  rrect18% 1.7x0.55 smd: 5(0,1.425)
  silkscreen extent -2.07,1.5 -1.87,1.7, body extent -2.3,-1.4 2.3,1.4, height 1.92
SW_PTS645SM43SMT [mm] "SMD, 4-Leads, Body 6x6mm"
  rrect8% 1.55x1.3 smd: 1(-3.975,2.25) 2(3.975,2.25) 3(-3.975,-2.25) 4(3.975,-2.25)
  body extent -4.5,-3 4.5,3, height 4.3
TI_Stacked_Overlay_Small [mil]
  silkscreen extent -418,-78 -237,98
TLMx1000_Yellow [mm] "SMD, 2-Leads, Body 1.6x0.8mm"
  rrect17% 0.6x0.8 smd: 1(-0.725,0) 2(0.725,0)
  silkscreen extent -0.98,-0.8 1.6,0.8, body extent -0.85,-0.45 0.85,0.45, height 0.65
TP_25MIL-SMT [mil]
  round 25 smd mask-2.5: 1(0,0)
TP_SM_1MM [mm] "1mm Test Point, SMT"
  round 1 smd paste-0.5: 1(0,0)
TP_VIA_060RND040 [mil] "TP_VIA_060RND040"
  round 60 hole 40: 1(0,0)
TSSOP-8 [mm] "TSSOP, 8-Leads, Body 3.1x4.5mm (max), Pitch 0.65mm, IPC Medium Density"
  rrect50% 1.7x0.35 smd: 1(-2.85,0.975) 2(-2.85,0.325) 3(-2.85,-0.325) 4(-2.85,-0.975) 5(2.85,-0.975) 6(2.85,-0.325) 7(2.85,0.325) 8(2.85,0.975)
  silkscreen extent -2.4,-1.55 1.6,1.75, body extent -3.2,-1.55 3.2,1.55, height 1.07
USON-8L [mm] "SON, 8-Leads, Body 3x2mm, Pitch 0.5mm"
  rrect40% 0.6x0.25 smd: 1(-1.4,0.75) 2(-1.4,0.25) 3(-1.4,-0.25) 4(-1.4,-0.75) 5(1.4,-0.75) 6(1.4,-0.25) 7(1.4,0.25) 8(1.4,0.75)
  rrect50% 0.2x1.6 smd: 9(0,0)
  silkscreen extent -1.55,-1.17 0.65,1.17, body extent -1.55,-1.05 1.55,1.05, height 0.6
WEEE_Minimum [mil] "WEEElie bin"
  silkscreen extent -95,-172 99,104
Wurth_61300311021 [mm] "Header, 2.54 mm, 3x1, R/A, TH"
  rect 1.6x1.6 hole 1.1: 1(-2.54,0)
  round 1.6 hole 1.1: 2(0,0) 3(2.54,0)
  silkscreen extent -4.25,-4.04 3.81,-1.5, body extent -3.81,-10.04 3.81,0.32, height 2.55

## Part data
C1 C100: library part CMP-0120082-1, "Multi-Layer Ceramic Capacitor 10pF C0G  ±1% 0402 Paper T/R", Manufacturer=Murata, Operating Temperature Range="-55°C to +125°C", TempCo=30ppm/°C, Temperature Characteristic=C0G, Tolerance_%=1%, ValueDisplayed=10pF
C2 C37 C38 C40 C41 C94 C95 C99 C106 C113 C116 C125 C126 C138 C140 C142 C143 C144 C146 C150 C152 C153 C158: library part CMP-0078241-1, "CAP, CERM, 0.1 µF, 10 V,+/- 10%, X7R, 0402", Cap_Case=0402, Manufacturer=Kemet, Supplier Part Number 1=399-3520-1-ND, TempCo=X7R, Tolerance_%=10%, Value2=10V, ValueDisplayed=0.1µF
C3 C18 C22: library part CMP-0120013-1, "Chip Multilayer Ceramic Capacitors for General Purpose, 0402, 1.0uF, X6S, 22%, 10%, 6.3V", Manufacturer=Murata, Operating Temperature Range="-55°C to +105°C", TempCo=22%, Temperature Characteristic=X6S, Tolerance_%=10%, ValueDisplayed=1.0uF
C4 C5 C7 C8 C10 C11 C12 C14 C16 C19 C21 C25 C26 C28 C29 C60 C101: library part CMP-0860563-1, "CAP, CERM, 0.22 µF, 16 V,+/- 10%, X7R, 0402", Cap_Case=0402, Manufacturer="Samsung Electro-Mechanics", TempCo=X7R, Tolerance_%=10%, Value2=16V, ValueDisplayed=0.22µF
C6: library part CMP-0006298-2, "CAP, CERM, 0.047 uF, 50 V, +/- 10%, X7R, 0402", Cap_Case=0402, Manufacturer=TDK, Supplier Part Number 1=445-7336-1-ND, TempCo=X7R, Tolerance_%=10%, Value1="0.06407 ohm", Value2=50V, ValueDisplayed=0.047uF
C9 C17 C20 C69 C70: library part CMP-0006526-2, "CAP, CERM, 2.2 uF, 16 V, +/- 10%, X6S, 0402", Cap_Case=0402, Manufacturer=MuRata, Supplier Part Number 1=GRM155C81C225KE11D-ND, TempCo=X6S, Tolerance_%=10%, Value1=Unknown, Value2=16V, ValueDisplayed=2.2uF
C13 C15 C23 C43 C44 C62 C72 C119 C120 C128 C129: library part CMP-0007295-4, "CAP, CERM, 10 uF, 10 V, +/- 20%, X6S, 0603", Cap_Case=0603, Manufacturer=MuRata, Supplier Part Number 1=490-7197-1-ND, TempCo=X6S, Tolerance_%=20%, Value1=Unknown, Value2=10V, ValueDisplayed=10uF
C24 C27: library part CMP-0120021-1, "Chip Multilayer Ceramic Capacitors for General Purpose, 0805, 4.7uF, X7R, 15%, 10%, 16V", Manufacturer=Murata, Operating Temperature Range="-55°C to +125°C", TempCo=15%, Temperature Characteristic=X7R, Tolerance_%=10%, ValueDisplayed=4.7uF
C30 C45: library part CMP-0078218-1, "CAP, CERM, 0.01 µF, 16 V,+/- 10%, X7R, 0402", Cap_Case=0402, Manufacturer=Kemet, Supplier Part Number 1=399-1038-1-ND, TempCo=X7R, Tolerance_%=10%, Value2=16V, ValueDisplayed=0.01µF
C31 C34: library part CMP-0064946-2, "CAP, CERM, 0.1 uF, 50 V,+/- 10%, X7R, 0402", Cap_Case=0402, Manufacturer=TDK, Supplier Part Number 1=445-173610-1-ND, TempCo=X7R, Tolerance_%=10%, Value1=Unknown, Value2=50V, ValueDisplayed=0.1uF
C32 C33: library part CMP-0006367-2, "CAP, CERM, 4.7 pF, 50 V, +/- 2%, C0G/NP0, 0402", Cap_Case=0402, Manufacturer=MuRata, Supplier Part Number 1=490-8102-1-ND, TempCo=C0G/NP0, Tolerance_%=2%, Value1=Unknown, Value2=50V, ValueDisplayed=4.7pF
C35: library part CMP-0085537-1, "CAP, CERM, 1 µF, 16 V,+/- 10%, X7R, 0603", Cap_Case=0603, Manufacturer="Samsung Electro-Mechanics", TempCo=X7R, Tolerance_%=10%, Value2=16V, ValueDisplayed=1µF
C36 C49 C50 C52 C53 C56 C57 C58 C59 C65 C75 C89 C91 C123 C133 C134: library part CMP-0006356-2, "CAP, CERM, 0.1 uF, 50 V, +/- 10%, X7R, AEC-Q200 Grade 1, 0402", Cap_Case=0402, Manufacturer=MuRata, Supplier Part Number 1=490-10672-1-ND, TempCo=X7R, Tolerance_%=10%, Value1=Unknown, Value2=50V, ValueDisplayed=0.1uF
C39: library part CMP-0006361-2, "CAP, CERM, 4700 pF, 50 V, +/- 10%, X7R, AEC-Q200 Grade 1, 0402", Cap_Case=0402, Manufacturer=MuRata, Supplier Part Number 1=490-4915-1-ND, TempCo=X7R, Tolerance_%=10%, Value1=Unknown, Value2=50V, ValueDisplayed=4700pF
C42 C105 C124: library part CMP-0006302-2, "CAP, CERM, 2.2 uF, 10 V, +/- 10%, X7S, 0402", Cap_Case=0402_065, Manufacturer=TDK, Supplier Part Number 1=445-9097-1-ND, TempCo=X7S, Tolerance_%=10%, Value1="0.005925 ohm", Value2=10V, ValueDisplayed=2.2uF
C46 C47: library part CMP-0006564-3, "CAP, CERM, 10 uF, 10 V, +/- 20%, X5R, 0402", Cap_Case=0402, Manufacturer=MuRata, TempCo=X5R, Tolerance_%=20%, Value1=Unknown, Value2=10V, ValueDisplayed=10uF
C48 C63: library part CMP-0078216-1, "CAP, TA, 47 µF, 10 V, +/- 10%, SMD", Cap_Case=3528-21, Manufacturer=Kemet, Supplier Part Number 1=399-9728-1-ND, Tolerance_%=10%, Value2=10V, ValueDisplayed=47µF
C51 C93 C108 C114 C127 C136 C137: library part CMP-0006272-2, "CAP, CERM, 1 uF, 10 V, +/- 10%, X6S, 0402", Cap_Case=0402, Manufacturer=TDK, Supplier Part Number 1=445-4978-1-ND, TempCo=X5R, Tolerance_%=10%, Value1=Unknown, Value2=16V, ValueDisplayed=1uF
C55: library part CMP-0008944-2, "CAP, CERM, 47 uF, 10 V, +/- 10%, X5R, 1206", Cap_Case=1206, Manufacturer=MuRata, Supplier Part Number 1=81-GRM31CR61A476KE5L, TempCo=X5R, Tolerance_%=10%, Value1=Unknown, Value2=10V, ValueDisplayed=47uF
C61 C79: library part CMP-0092150-1, "Chip Multilayer Ceramic Capacitors for General Purpose, 1206, 22uF, X7R, 15%, 20%, 6.3V", Manufacturer=Murata, Operating Temperature Range="-55°C to +125°C", TempCo=15%, Temperature Characteristic=X7R, Tolerance_%=20%, ValueDisplayed=22uF
C66 C73: library part CMP-0007398-4, "CAP, CERM, 0.47 uF, 16 V, +/- 10%, X7R, 0603", Cap_Case=0603, Manufacturer=MuRata, Supplier Part Number 1=490-3295-1-ND, TempCo=X7R, Tolerance_%=10%, Value1=Unknown, Value2=16V, ValueDisplayed=0.47uF
C67 C74: library part CMP-0006470-2, "CAP, CERM, 470 pF, 50 V, +/- 5%, C0G/NP0, 0402", Cap_Case=0402, Manufacturer=MuRata, Supplier Part Number 1=490-1297-1-ND, TempCo=C0G/NP0, Tolerance_%=5%, Value1=Unknown, Value2=50V, ValueDisplayed=470pF
C68: library part CMP-0008940-2, "CAP, CERM, 47 uF, 6.3 V, +/- 20%, X5R, 1206", Cap_Case=1206, Manufacturer=MuRata, Supplier Part Number 1=490-3907-1-ND, TempCo=X5R, Tolerance_%=20%, Value1="0.003 ohm", Value2=6.3V, ValueDisplayed=47uF
C84 C92: library part CMP-0064967-2, "CAP, CERM, 0.47 uF, 10 V,+/- 10%, X7S, 0402", Cap_Case=0402, Manufacturer=MuRata, Supplier Part Number 1=490-14427-1-ND, TempCo=X7S, Tolerance_%=10%, Value1=Unknown, Value2=10V, ValueDisplayed=0.47uF
C85: library part CMP-0078265-1, "CAP, CERM, 0.22 µF, 16 V,+/- 10%, X7R, AEC-Q200 Grade 1, 0402", Cap_Case=0402, Manufacturer=MuRata, Supplier Part Number 1=490-10671-1-ND, TempCo=X7R, Tolerance_%=10%, Value2=16V, ValueDisplayed=0.22µF
C86 C96: library part CMP-0007497-5, "CAP, CERM, 10 uF, 10 V, +/- 10%, X5R, 0603", Cap_Case=0603, Manufacturer=MuRata, Supplier Part Number 1=81-GRM188Z71A106MA3D, TempCo=X7R, Tolerance_%=20%, Value1=Unknown, Value2=10V, ValueDisplayed=10uF
C88 C90 C102 C115 C118: library part CMP-0006352-2, "CAP, CERM, 0.01 uF, 25 V, +/- 10%, X7R, 0402", Cap_Case=0402, Manufacturer=MuRata, Supplier Part Number 1=490-6043-2-ND, TempCo=X7R, Tolerance_%=10%, Value1=Unknown, Value2=25V, ValueDisplayed=0.01uF
C97 C98: library part CMP-0860185-1, "CAP, CERM, 8 pF, 50 V,+/- 6.25%, C0G/NP0, 0402", Cap_Case=0402, Manufacturer=Yageo, TempCo=C0G/NP0, Tolerance_%=6.25%, Value2=50V, ValueDisplayed=8pF
C121 C122 C130 C131: library part CMP-0008676-3, "CAP, CERM, 22 uF, 10 V, +/- 20%, X6S, 1206", Cap_Case=1206_180, Manufacturer=TDK, Supplier Part Number 1=445-14755-1-ND, TempCo=X6S, Tolerance_%=20%, Value1="0.002398 ohm", Value2=10V, ValueDisplayed=22uF
C132: library part CMP-0006218-2, "CAP, CERM, 220 pF, 50 V, +/- 5%, C0G/NP0, 0402", Cap_Case=0402, Manufacturer="Wurth Elektronik", Supplier Part Number 1=732-7477-1-ND, TempCo=C0G/NP0, Tolerance_%=5%, Value1=Unknown, Value2=50V, ValueDisplayed=220pF
C135: library part CMP-0007497-5, "CAP, CERM, 10 uF, 10 V, +/- 20%, X7R, 0603", Cap_Case=0603, Manufacturer=MuRata, Supplier Part Number 1=81-GRM188Z71A106MA3D, TempCo=X7R, Tolerance_%=20%, Value1=Unknown, Value2=10V, ValueDisplayed=10uF
C139 C141 C145: library part CMP-0007058-4, "CAP, CERM, 4.7 uF, 10 V, +/- 10%, X7S, 0603", Cap_Case=0603, Manufacturer=TDK, Supplier Part Number 1=445-14258-1-ND, TempCo=X7S, Tolerance_%=10%, Value1=Unknown, Value2=10V, ValueDisplayed=4.7uF
C147 C148: library part CMP-0087060-3, "Cap Ceramic 8pF 50V C0G 0.5pF SMD 0402 125C Paper T/R", Manufacturer="Murata Electronics North America", TempCo=30ppm/°C
C149 C151: library part CMP-0007136-5, "CAP, CERM, 1 uF, 16 V, +/- 10%, X7R, AEC-Q200 Grade 1, 0603", Cap_Case=0603, Manufacturer=MuRata, Supplier Part Number 1=490-5241-6-ND, TempCo=X7R, Tolerance_%=10%, Value1=Unknown, Value2=16V, ValueDisplayed=1uF
C157: library part CMP-0007995-2, "CAP, CERM, 10 uF, 16 V, +/- 10%, X7R, 0805", Cap_Case=0805, Manufacturer="Samsung Electro-Mechanics", TempCo=X7R, Tolerance_%=10%, Value1=Unknown, Value2=16V, ValueDisplayed=10uF
D1 D2 D8 D12: library part CMP-0078758-2, "Diode, Schottky, 30 V, 2 A, AEC-Q101, SOD-128", Manufacturer=Nexperia, Value1=2A, Value2=0.36V
D3 D10: library part CMP-0078196-2, "LED, Yellow, SMD", Color=yellow, Manufacturer=Vishay-Semiconductor, Power_TotalModule=40mW, Value1=.04W, Value2=1.8V
D4: library part CMP-0078243-3, "Diode, TVS, Uni, 5.8 V, 10.5 Vc, AEC-Q101, SMB", Manufacturer=Littelfuse, Value1=0.55W
D5 D6 D7: library part CMP-0067682-2, "LED, Green, SMD", Color=Green, Manufacturer=Kingbright, Power_TotalModule=75mW, Value1=0.075W, Value2=2.1V
D9: library part CMP-0067681-2, "LED, Red, SMD", Color=Red, Manufacturer=Kingbright, Power_TotalModule=75mW, Value1=0.075W, Value2=1.95V
F1: library part CMP-0003458-2, "Fuse, 5 A, 32VAC/VDC, SMD", Irating_A=5A, Manufacturer=Littelfuse, PartNumber=0440005.WR, Supplier Part Number 1=F1608CT-ND
FB1 FB2: library part CMP-0003364-1, "Ferrite Bead, 30 ohm @ 100 MHz, 4 A, 0805", Manufacturer=MuRata, Supplier Part Number 1=490-11049-1-ND, Value1="0.014 ohm", Value2=4A, ValueDisplayed="30 ohm"
FID1 FID2 FID3 FID4 FID5 FID6: library part CMP-0077181-1, "Fiducial mark.  There is nothing to buy or mount.", Manufacturer=N/A
J1: library part CMP-0054795-1, "Header, 2.54 mm, 3x1, Gold, R/A, TH", Color=Black, Manufacturer="Wurth Elektronik", Supplier Part Number 1=732-5336-ND
J2: library part CMP-0120118-1, Current_A=4A, Digikey Part Number=WM50015-07-ND, Manufacturer=Molex, Mouser Part Number=538-22-28-8072, Operating Temperature Range="-40°C to +80°C", Voltage_V=600V
J3: library part CMP-0087785-1, "CONN HEADER R/A 3POS 1.27MM", Current_A=1A, Manufacturer=Harwin
J4: library part CMP-0087187-1, "CONN HDR 1.27MM R/A AU 4POS", Current_A=1A, Manufacturer="Harwin Inc."
J5 J10: library part CMP-0055293-1, "Connector, Receptacle, Micro-USB Type B, R/A, Bottom Mount SMT", Manufacturer=Molex, Supplier Part Number 1=WM1399CT-ND
J6: library part CMP-0075524-1, "Receptacle, 0.5 mm, 30x2, Gold, TH", Color=Black, Manufacturer=Samtec, Supplier Part Number 1=SAM8180-ND
J7: library part CMP-0078270-1, "DC POWER JACK, R/A, TH", Color=Black, Current_A=5A, Manufacturer="CUI Inc.", Supplier Part Number 1=CP-002AH-ND, Voltage_V=4.5-5.5V
J8: library part CMP-0049921-1, Current_A=1A, Digikey Part Number=2073-BC050-12A-K0-0200-0160-0480-LBCT-ND, Manufacturer=GCT, Mouser Part Number=640-BC05012AK2016LB, Operating Temperature Range="-40°C to +105°C", Voltage_V=250V
J9: library part CMP-0049930-1, Current_A=1A, Digikey Part Number=2073-BC084-12-A-0390-L-CCT-ND, Manufacturer=GCT, Mouser Part Number=640-BC084-12-A0390LC, Operating Temperature Range="-40°C to +105°C", Voltage_V=250V
L1 L5 L6: library part CMP-0095018-1, "100nH Shielded Multilayer Inductor 4A 19mOhm Max 0806 (2016 Metric)", Digikey Part Number=490-LQM2MPZR10MJHLCT-ND, Manufacturer=Murata, Mouser Part Number=81-LQM2MPZR10MJHL, Operating Temperature Range="-55°C to +125°C", Self Resonant Frequency=200MHz, Test Frequency=1MHz, Tolerance_%=20%
L2 L3 L7: library part CMP-0081523-1, "Ferrite Bead, 600 ohm @ 100 MHz, 0.3 A, 0402", Manufacturer=MuRata, Supplier Part Number 1=490-3998-1-ND, Value1="0.7 ohm", Value2=0.3A, ValueDisplayed="600 ohm"
L8 L9: library part CMP-0078934-1, "Inductor, Ferrite Bead, Ferrite, 2.2 A, 0.035 ohm, AEC-Q200 Grade 1, SMD", Manufacturer=MuRata, Supplier Part Number 1=490-16506-1-ND, Value1="0.035 ohm", Value2=2.2A
L14 L15: library part CMP-0092096-1, "470nH Shielded Wirewound Inductor 3A 42mOhm Max 0805 (2012 Metric)", Digikey Part Number=490-17727-1-ND, Manufacturer=Murata, Mouser Part Number=81-DFE201210U-R47MP2, Operating Temperature Range="-40°C to +125°C", Part Number=DFE201210U-R47M{}P2, Test Frequency=1MHz, Tolerance_%=20%
Logo1: library part CMP-0074838-1, "Texas Instrument Corporate Signature"
Logo2: library part CMP-0074844-1
LOGO3: library part CMP-0074847-1, "FCC_disclaimer"
Logo4: library part CMP-0074769-1
Q1 Q3 Q4: library part CMP-0091833-1, "N-Channel 20V 250mA (Ta) 500mW (Ta) Surface Mount VESM", Digikey Part Number=SSM3K35AMFVL3FCT-ND, Drain To Source Breakdown Voltage=20V, Input Capacitace At Vds="18pF @ 10V", Manufacturer=Toshiba, Mouser Part Number=757-SSM3K35AMFVL3F, Operating Temperature Range="to +150°C", Power_W=150mW, Pulse Drain Current=600mA, Typ Forward Diode Voltage=0.8V
Q2: library part CMP-0000948-2, "MOSFET, N-CH, 100 V, 0.17 A, SOT-323", Alternate Manufacturer=None, Manufacturer="Diodes Inc.", Supplier Part Number 1=BSS123W-FDICT-ND, Value1=1
R1 R30 R31 R32 R129: library part CMP-0025884-3, "RES, 0, 5%, 0.125 W, 0603", Manufacturer=Vishay/Beyschlag, Power_W=125mW, Supplier Part Number 1=MCT0603-0.0-ZZCT-ND, TempCo=ppm/C, Tolerance_%=5%, Value2=0.125W, Value_Code=0000, ValueDisplayed=0
R2 R5 R7 R8 R10 R12 R14 R17 R22 R23 R27 R54 R65 R71 R72 R76 R81 R82 R90 R91 R94 R97 R98 R101 R102 R103 R104 R105 R106 R107 R112 R113 R114 R115 R116 R117 R123 R135 R136 R138 R142 R148 R150 R152 R157 R158 R161 R162 R165 R167 R168 R184 R203 R206 R218 R231: library part CMP-0025958-3, "RES, 10.0 k, 1%, 0.063 W, AEC-Q200 Grade 0, 0402", Manufacturer=Vishay-Dale, Power_W=63mW, Supplier Part Number 1=541-10.0KLCT-ND, TempCo="100 ppm/C", Tolerance_%=1%, Value2=0.063W, Value_Code=10k0, ValueDisplayed=10.0k
R3 R15 R18 R19 R24 R25 R26 R29 R34 R37 R38 R39 R40 R41 R42 R43 R52 R53 R55 R56 R57 R58 R59 R60 R61 R62 R63 R67 R69 R78 R80 R88 R108 R109 R110 R111 R127 R128 R137 R139 R151 R159 R160 R170 R181 R188 R189 R190 R197 R199 R214 R216 R217 R219 R220 R221 R222 R223 R224 R225 R226 R227 R228 R229 R230 R241 R242 R243 R259 R261: library part CMP-0002710-1, "0 Ohms Jumper Chip Resistor 0402 (1005 Metric) Automotive AEC-Q200 Thick Film", Digikey Part Number=P0.0JCT-ND, Manufacturer=Panasonic, Mouser Part Number=667-ERJ-2GE0R00X, Operating Temperature Range="-55°C to +155°C", Power=100mW
R4 R9 R20 R44 R49 R75: library part CMP-0001699-1, "10 kOhms ±1% 0.063W, 1/16W Chip Resistor 0402 (1005 Metric) Moisture Resistant Thick Film", Digikey Part Number=311-10.0KLRCT-ND, Manufacturer=Yageo, Mouser Part Number=603-RC0402FR-0710KL, Operating Temperature Range="-55°C to +155°C", Power_W=63mW, TempCo=100ppm/°C, Tolerance_%=1%
R6 R33: library part CMP-0026938-5, "RES, 4.7 k, 5%, 0.063 W, AEC-Q200 Grade 0, 0402", Manufacturer=Vishay-Dale, Power_W=63mW, Supplier Part Number 1=541-4.7KJCT-ND, TempCo="200 ppm/C", Tolerance_%=5%, Value2=0.063W, Value_Code=4k70, ValueDisplayed=4.7k
R11 R99 R120 R215: library part CMP-0025950-3, "RES, 100 k, 1%, 0.063 W, AEC-Q200 Grade 0, 0402", Manufacturer=Vishay-Dale, Power_W=63mW, Supplier Part Number 1=541-100KLCT-ND, TempCo="100 ppm/C", Tolerance_%=1%, Value2=0.063W, Value_Code=100k
R13 R16: library part CMP-0026542-2, "RES, 750, 1%, 0.063 W, AEC-Q200 Grade 0, 0402", Manufacturer=Vishay-Dale, Power_W=63mW, Supplier Part Number 1=541-750LCT-ND, TempCo="100 ppm/C", Tolerance_%=1%, Value2=0.063W, Value_Code=750R, ValueDisplayed=750
R21 R70 R83 R191 R194 R195 R196 R233 R237: library part CMP-0026071-3, "RES, 1.00 k, 1%, 0.063 W, AEC-Q200 Grade 0, 0402", Manufacturer=Vishay-Dale, Power_W=63mW, Supplier Part Number 1=541-1.00KLCT-ND, TempCo="100 ppm/C", Tolerance_%=1%, Value2=0.063W, Value_Code=1k00, ValueDisplayed=1.00k
R28 R66 R141 R171 R172 R174 R179 R252: library part CMP-0078212-1, "RES, 510, 5%, 0.1 W, AEC-Q200 Grade 0, 0402", Manufacturer=Panasonic, Power_W=100mW, Supplier Part Number 1=P510JCT-ND, TempCo="200 ppm/C", Tolerance_%=5%, Value2=0.1W, Value_Code=510R, ValueDisplayed=510
R35 R77 R119 R173 R176 R198: library part CMP-0093147-1, "Res Jumper Thick Film 0402 0 Ohm 5% 1/16W Molded SMD Paper T/R", Digikey Part Number=YAG1279CT-ND, Manufacturer=Yageo, Mouser Part Number=603-RC0402JR-070RP, Operating Temperature Range="-55°C to +155°C", Power_W=63mW
R36: library part CMP-0120085-1, "40.2 kOhms ±1% 0.063W, 1/16W Chip Resistor 0402 (1005 Metric) Thick Film", Digikey Part Number=541-4097-1-ND, Manufacturer=Vishay, Mouser Part Number=71-CRCW040240K2FKEDC, Octopart Part Number=b2087a69b6ae6dcf, Operating Temperature Range="-55°C to +155°C", Power_W=63mW, TempCo=100ppm/°C, Tolerance_%=1%
R45 R46 R47 R48 R51 R93: library part CMP-0120016-1, "33.2 Ohms ±1% 0.063W, 1/16W Chip Resistor 0402 (1005 Metric) Thin Film", Digikey Part Number=13-RT0402FRE0733R2LCT-ND, Manufacturer=Yageo, Mouser Part Number=603-RT0402FRE0733R2L, Operating Temperature Range="-55°C to +155°C", Power_W=63mW, TempCo=50ppm/°C, Tolerance_%=1%
R50: library part CMP-0120015-1, "General Purpose Chip Resistor Thick Film 0402 47.5kOhm 1% Paper T/R", Digikey Part Number=13-RC0402FR-1047K5LCT-ND, Manufacturer=YAGEO, Mouser Part Number=603-RC0402FR-1047K5L, Operating Temperature Range="-55°C to +155°C", Power_W=63mW, TempCo=100ppm/°C, Tolerance_%=1%
R64 R213: library part CMP-0026878-3, "RES, 220, 5%, 0.063 W, AEC-Q200 Grade 0, 0402", Manufacturer=Vishay-Dale, Power_W=63mW, Supplier Part Number 1=541-220JCT-ND, TempCo="200 ppm/C", Tolerance_%=5%, Value2=0.063W, Value_Code=220R, ValueDisplayed=220
R68 R79: library part CMP-0026491-2, "RES, 61.9, 1%, 0.063 W, AEC-Q200 Grade 0, 0402", Manufacturer=Vishay-Dale, Power_W=63mW, Supplier Part Number 1=541-61.9LCT-ND, TempCo="100 ppm/C", Tolerance_%=1%, Value2=0.063W, Value_Code=61R9, ValueDisplayed=61.9
R73 R74: library part CMP-0120018-1, "100 kOhms ±1% 0.063W, 1/16W Chip Resistor 0402 (1005 Metric) Thick Film", Digikey Part Number=1292-WR04X1003FTLCT-ND, Manufacturer="Walsin Technology", Mouser Part Number=791-WR04X1003FTL, Operating Temperature Range="-55°C to +155°C", Power_W=63mW, TempCo=100ppm/°C, Tolerance_%=1%
R86: library part CMP-0098279-1, "RES Thick Film SMD 1kΩ 1% 1/16W 0402 100ppm/°C", Digikey Part Number=311-1.00KLRCT-ND, Manufacturer=Yageo, Mouser Part Number=603-RC0402FR-071KL, Operating Temperature Range="-55°C to +155°C", Power_W=63mW, TempCo=100ppm/°C, Tolerance_%=1%
R121: library part CMP-0120089-1, "68 kOhms ±1% 0.063W, 1/16W Chip Resistor 0402 (1005 Metric) Thick Film", Digikey Part Number=1292-WR04X6802FTLCT-ND, Manufacturer="Walsin Technology", Mouser Part Number=791-WR04X6802FTL, Operating Temperature Range="-55°C to +155°C", Power_W=63mW, TempCo=100ppm/°C, Tolerance_%=1%
R122 R124 R125 R126 R186 R187 R209 R248 R249 R251: library part CMP-0026299-2, "RES, 33.2, 1%, 0.063 W, AEC-Q200 Grade 0, 0402", Manufacturer=Vishay-Dale, Power_W=63mW, Supplier Part Number 1=541-33.2LCT-ND, TempCo="100 ppm/C", Tolerance_%=1%, Value2=0.063W, Value_Code=33R2, ValueDisplayed=33.2
R134: library part CMP-0098430-1, "Res Metal Strip 1206 0.02 Ohm 1% 1/4W ±75ppm/°C Molded SMD SMD T/R", Digikey Part Number=541-WSL1206R0200FEBCT-ND, Manufacturer="Vishay Dale", Mouser Part Number=71-WSL1206-0.02-E3, Octopart Part Number=bfee76eb40e46029, Operating Temperature Range="-65°C to +170°C", Power_W=250mW, TempCo=75ppm/°C, Tolerance_%=1%
R169: library part CMP-0026993-2, "RES, 100, 5%, 0.1 W, AEC-Q200 Grade 0, 0402", Manufacturer=Panasonic, Power_W=100mW, Supplier Part Number 1=P100JCT-ND, TempCo="200 ppm/C", Tolerance_%=5%, Value2=0.1W, Value_Code=100R, ValueDisplayed=100
R175 R177 R201 R238 R244: library part CMP-0092204-1, "100 kOhms ±1% 0.063W, 1/16W Chip Resistor 0402 (1005 Metric)  Thick Film", Digikey Part Number=541-3960-1-ND, Manufacturer=Vishay, Mouser Part Number=71-CRCW0402100KFKEDC, Operating Temperature Range="-55°C to +155°C", Power_W=63mW, TempCo=100ppm/°C, Tolerance_%=1%
R178 R180: library part CMP-0094741-1, "Res Thick Film 0402 18K Ohm 1% 1/16W ±100ppm/°C Molded SMD Paper T/R", Digikey Part Number=541-4757-1-ND, Manufacturer=Vishay, Mouser Part Number=71-CRCW040218K0FKEDC, Operating Temperature Range="-55°C to +155°C", Power_W=63mW, TempCo=100ppm/°C, Tolerance_%=1%
R185: library part CMP-0026890-5, "RES, 2.2 k, 5%, 0.063 W, AEC-Q200 Grade 0, 0402", Manufacturer=Vishay-Dale, Power_W=63mW, Supplier Part Number 1=541-2.2KJCT-ND, TempCo="200 ppm/C", Tolerance_%=5%, Value2=0.063W, Value_Code=2k20, ValueDisplayed=2.2k
R192 R193 R200: library part CMP-0098431-1, "40 mOhms ±1% 0.25W, 1/4W Chip Resistor Automotive AEC-Q200, Current Sense, Moisture Resistant, Pulse Withstanding Metal Element", Digikey Part Number=WSL1206R0400FEB-ND, Manufacturer=Vishay, Mouser Part Number=71-WSL1206-0.04-E3, Operating Temperature Range="-65°C to +170°C", Power_W=250mW, TempCo=75ppm/°C, Tolerance_%=1%
R202: library part CMP-0026404-2, "RES, 49.9, 1%, 0.063 W, AEC-Q200 Grade 0, 0402", Manufacturer=Vishay-Dale, Power_W=63mW, Supplier Part Number 1=541-49.9LCT-ND, TempCo="100 ppm/C", Tolerance_%=1%, Value2=0.063W, Value_Code=49R9, ValueDisplayed=49.9
R204 R207: library part CMP-0026557-2, "RES, 7.87 k, 1%, 0.063 W, AEC-Q200 Grade 0, 0402", Manufacturer=Vishay-Dale, Power_W=63mW, Supplier Part Number 1=541-7.87KLCT-ND, TempCo="100 ppm/C", Tolerance_%=1%, Value2=0.063W, Value_Code=7k87, ValueDisplayed=7.87k
R205 R208: library part CMP-0026574-2, "RES, 82.5 k, 1%, 0.063 W, AEC-Q200 Grade 0, 0402", Manufacturer=Vishay-Dale, Power_W=63mW, Supplier Part Number 1=541-82.5KLCT-ND, TempCo="100 ppm/C", Tolerance_%=1%, Value2=0.063W, Value_Code=82k5, ValueDisplayed=82.5k
R234: library part CMP-0026413-2, "RES, 4.87 k, 1%, 0.063 W, AEC-Q200 Grade 0, 0402", Manufacturer=Vishay-Dale, Power_W=63mW, Supplier Part Number 1=541-4.87KLCT-ND, TempCo="100 ppm/C", Tolerance_%=1%, Value2=0.063W, Value_Code=4k87, ValueDisplayed=4.87k
R236 R239: library part CMP-0078210-2, "RES, 330 k, 1%, 0.063 W, AEC-Q200 Grade 0, 0402", Manufacturer=Vishay-Dale, Power_W=63mW, Supplier Part Number 1=541-330KLCT-ND, TempCo="100 ppm/C", Tolerance_%=1%, Value2=0.063W, Value_Code=330k
R260: library part CMP-0078244-2, "RES, 30.0 k, 1%, 0.063 W, AEC-Q200 Grade 0, 0402", Manufacturer=Vishay-Dale, Power_W=63mW, Supplier Part Number 1=541-30.0KLCT-ND, TempCo="100 ppm/C", Tolerance_%=1%, Value2=0.063W, Value_Code=30k0, ValueDisplayed=30.0k
S1: library part CMP-0002304-1, "Switch, SPST, Slide, Off-On, 6 Pos, 0.025A, 24V, SMD", CurrentRating_mA=25A, Manufacturer="CTS Electrocomponents", Supplier Part Number 1=CT2186LPST-ND
S2: library part CMP-0079642-1, "Switch, SPST-NO, Off-Mom, 0.05 A, 12 VDC, SMD", CurrentRating_mA=50A, Manufacturer="C&K Components", Supplier Part Number 1=CKN9112CT-ND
